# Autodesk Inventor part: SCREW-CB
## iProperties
Created: 2006-07
Part Number: SCREW-CB
Material: Steel, High Strength Low Alloy
Document SubType Name: Modeling
Designer: rollin42
Density: 7.84 g/cm^3
Stock Number: SCREW-CB
Author: rollin42
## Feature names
1. Extrusion1
2. Extrusion2
3. Coil1
4. Extrusion3
5. Revolution1
6. Hole1
